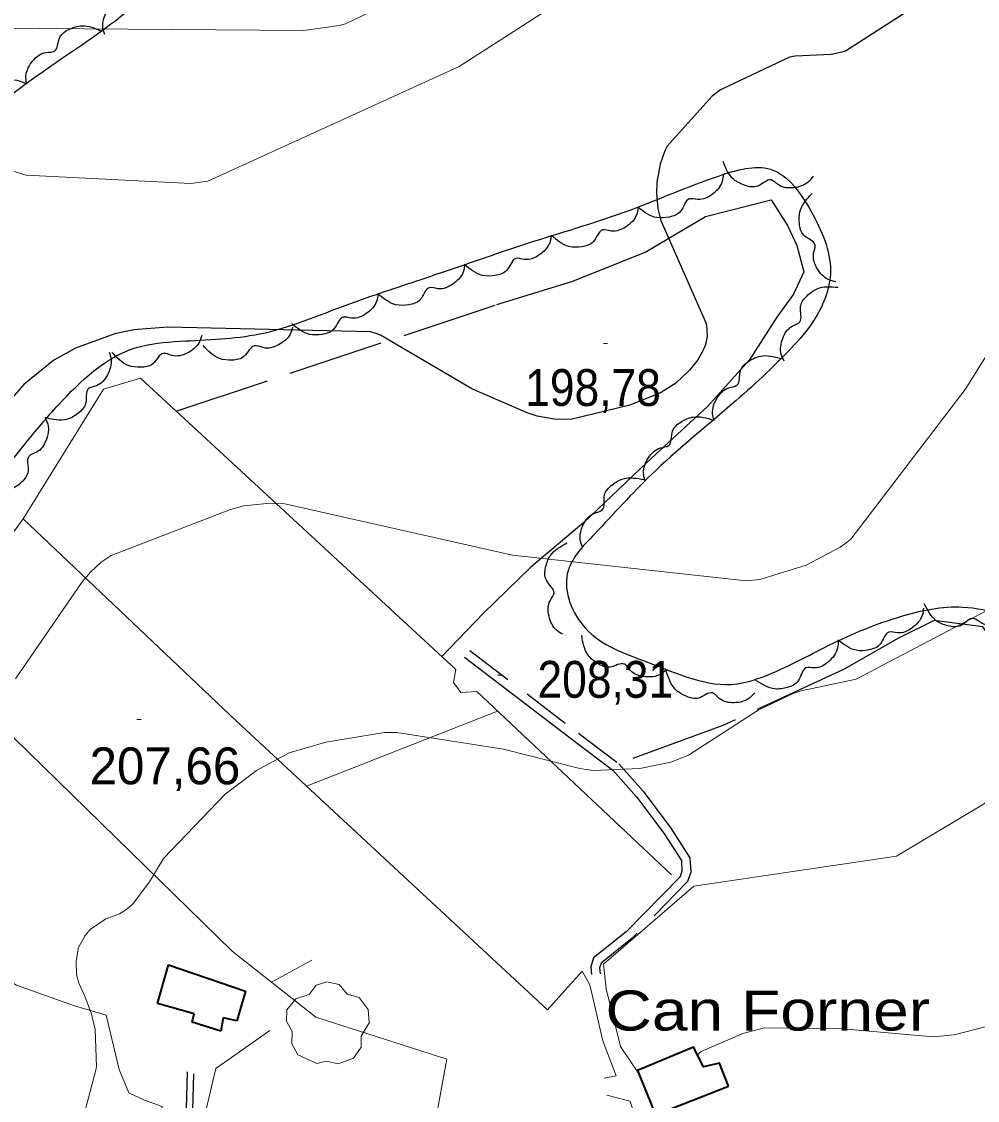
# Model space of a CAD drawing. Extents: x 480269 to 484877, y 4383588 to 4386804.
# Drawn here: x 482297.9 to 482524.9, y 4385133.1 to 4385389.2 of the extents above; entities that cross this region are included whole.
import ezdxf

# ---------------------------------------------------------------- set-up
doc = ezdxf.new("R2010")
doc.units = 0
doc.header["$LTSCALE"] = 3.8
doc.linetypes.add('LONG_DASHED', pattern=[7.5, 6, -1.5])
doc.linetypes.add('MEDIUM_DASHED', pattern=[4.5, 3, -1.5])
for name, color, linetype, lineweight in [('25', 7, 'LONG_DASHED', 25), ('27', 7, 'Continuous', 25), ('29', 7, 'Continuous', 13), ('38', 7, 'Continuous', 25), ('47', 7, 'Continuous', 35), ('49', 7, 'LONG_DASHED', 35), ('51', 7, 'Continuous', 13), ('7', 7, 'Continuous', 13), ('8', 7, 'Continuous', 25), ('9', 7, 'Continuous', 13)]:
    doc.layers.add(name, color=color, linetype=linetype, lineweight=lineweight)
doc.layers.add('5', color=7, linetype='Continuous')

msp = doc.modelspace()

# ---------------------------------------------------------------- linework, layer by layer
at = {"layer": '25'}
for points in [[(482334.67, 4385296.71), (482410.77, 4385322), (482428.81, 4385327.56), (482446.01, 4385334.45), (482460.32, 4385342.91), (482475.93, 4385346.89), (482479.8, 4385340.74), (482482, 4385336.01), (482483.67, 4385329.75), (482481.22, 4385324.46), (482477.28, 4385319.01), (482470.76, 4385308.85), (482460.91, 4385297.89), (482446.35, 4385284.46), (482431.47, 4385270.29), (482418.89, 4385259.64), (482407.54, 4385248.66), (482397.7, 4385238.43)], [(482545.45, 4385218.77), (482535.72, 4385231.68), (482530.93, 4385238.87), (482526.16, 4385245.48), (482514.65, 4385247.03), (482506.2, 4385242.78), (482493.24, 4385235.48), (482464.45, 4385222.09), (482439.95, 4385213.07)]]:
    msp.add_lwpolyline(points, dxfattribs=at)
at = {"layer": '27'}
for points in [[(482134.14, 4385639.56), (482145.42, 4385616.05), (482167.98, 4385611.34), (482199.94, 4385629.21), (482256.34, 4385654.6), (482299.58, 4385676.23), (482309.92, 4385675.29), (482324.96, 4385660.25), (482353.16, 4385626.39), (482366.32, 4385607.58), (482355.04, 4385597.24), (482347.52, 4385585.01), (482347.52, 4385561.5), (482356.92, 4385553.04), (482382.29, 4385553.98), (482400.15, 4385553.98), (482414.25, 4385537.05), (482418.01, 4385522), (482407.67, 4385512.6), (482383.23, 4385513.54), (482370.08, 4385507.9), (482358.8, 4385494.73), (482359.74, 4385477.8), (482342.82, 4385454.29), (482257.28, 4385376.24), (482191.48, 4385317.93), (482156.7, 4385290.66), (482136.02, 4385273.73), (482119.1, 4385272.79), (482113.46, 4385285.02), (482126.62, 4385312.29), (482143.54, 4385346.14), (482160.46, 4385378.12), (482156.7, 4385395.99), (482134.14, 4385407.27), (482113.46, 4385416.68), (482093.72, 4385412.91), (482087.14, 4385401.63), (482072.1, 4385398.81), (482050.48, 4385407.27), (482035.44, 4385408.21), (482021.34, 4385395.05), (482005.36, 4385398.81), (482011, 4385429.84), (482001.6, 4385476.86), (481971.52, 4385519.18), (481936.74, 4385563.38), (481930.16, 4385579.37), (481941.44, 4385597.24), (481940.5, 4385616.99), (481916.06, 4385648.96), (481908.54, 4385674.35), (481928.28, 4385695.98), (481936.74, 4385694.1), (481957.42, 4385664.01), (481967.76, 4385648.02), (481979.04, 4385640.5), (481992.2, 4385648.02), (482008.18, 4385667.77), (482022.28, 4385668.71), (482035.44, 4385653.66), (482062.7, 4385651.78), (482096.54, 4385655.54), (482120.04, 4385653.66), (482134.14, 4385639.56)], [(482987.06, 4385196.22), (482962.01, 4385203.27), (482933.82, 4385208.75), (482918.16, 4385210.32), (482910.33, 4385217.37), (482911.12, 4385227.55), (482911.12, 4385236.17), (482900.16, 4385244), (482857.87, 4385258.89), (482836.73, 4385270.64), (482824.21, 4385265.15), (482832.82, 4385247.14), (482820.29, 4385239.3), (482767.05, 4385239.3), (482715.37, 4385240.87), (482694.23, 4385249.49), (482675.44, 4385265.94), (482679.36, 4385287.09), (482678.57, 4385302.75), (482650.39, 4385311.37), (482636.29, 4385330.17), (482633.95, 4385351.32), (482617.5, 4385368.55), (482588.53, 4385379.52), (482572.87, 4385393.62), (482558.78, 4385411.63), (482539.21, 4385429.65), (482525.9, 4385448.45), (482516.5, 4385468.82), (482492.23, 4385501.72), (482482.83, 4385522.08), (482488.31, 4385537.75), (482533.73, 4385569.87), (482542.34, 4385576.13)], [(482625.51, 4385282.56), (482642.43, 4385259.65), (482650.38, 4385244.64), (482647.78, 4385242.37), (482636.62, 4385237.32), (482619.6, 4385231), (482606.07, 4385227.49), (482592.32, 4385225.27), (482576.02, 4385223.66), (482565.3, 4385225.16), (482544.25, 4385237.98), (482530.74, 4385248.12), (482521.45, 4385250.21), (482506.84, 4385248), (482489.75, 4385241.2), (482474.05, 4385233.67), (482467.83, 4385231.98), (482446.42, 4385237.18), (482431.83, 4385245.15), (482427.52, 4385258.1), (482433.95, 4385267.51), (482447.44, 4385281.6), (482466.7, 4385298.44), (482480.68, 4385311.65), (482486, 4385318.16), (482489.98, 4385329.2), (482485.82, 4385343.36), (482475.74, 4385354.14), (482463.65, 4385352.6), (482442.18, 4385344.35), (482419.61, 4385337.03), (482392.84, 4385327.98), (482375.42, 4385322.04), (482354.47, 4385315.04), (482335.63, 4385313.3), (482324.91, 4385311.71), (482306.75, 4385298.27), (482298.77, 4385288.95), (482284.61, 4385269.24), (482273.64, 4385250.87), (482262.03, 4385234.12), (482247.6, 4385214.12), (482240.37, 4385209.68), (482231.84, 4385210.09), (482210.78, 4385220.1), (482179.62, 4385233.3), (482175.12, 4385239.41), (482174.28, 4385251.32), (482183.7, 4385264.71), (482206.93, 4385288.25), (482225.02, 4385306.72), (482255.15, 4385335.95), (482274.61, 4385354.56), (482305.02, 4385378.68), (482323.6, 4385392.1), (482343.47, 4385412.74), (482356.09, 4385425.44), (482370.63, 4385438.23), (482383.14, 4385448.74), (482409.87, 4385473.1), (482434.85, 4385494.28), (482448.48, 4385499.91), (482458.21, 4385495.14), (482469.07, 4385482.48), (482479.65, 4385471.01), (482489.49, 4385457.47), (482504.85, 4385438.05), (482518.31, 4385421.58), (482537.64, 4385396.47), (482552.32, 4385375.39), (482572.69, 4385353.07), (482605.31, 4385309.46), (482625.51, 4385282.56)], [(482317.71, 4385386.09), (482317.25, 4385387.81), (482318.15, 4385391.49), (482320.81, 4385394.05), (482322.73, 4385394.77), (482323.4, 4385398.26), (482325.26, 4385400.6), (482327.96, 4385401.95), (482332.91, 4385401.59)], [(482299.1, 4385374.63), (482298.98, 4385376.4), (482300.58, 4385379.84), (482303.68, 4385381.84), (482305.71, 4385382.17), (482307.04, 4385385.47), (482309.32, 4385387.39), (482312.24, 4385388.2), (482317.02, 4385386.88)], [(482282.12, 4385361.1), (482281.88, 4385362.86), (482283.26, 4385366.4), (482286.23, 4385368.58), (482288.23, 4385369.04), (482289.35, 4385372.42), (482291.51, 4385374.48), (482294.37, 4385375.47), (482299.22, 4385374.46)], [(482485.92, 4385352.51), (482484.78, 4385351.14), (482481.26, 4385349.74), (482477.63, 4385350.43), (482475.93, 4385351.59), (482472.7, 4385350.11), (482469.72, 4385350.29), (482467.05, 4385351.71), (482464.49, 4385355.96)], [(482464.58, 4385352.97), (482464.3, 4385351.21), (482461.98, 4385348.21), (482458.51, 4385346.96), (482456.46, 4385347.08), (482454.43, 4385344.16), (482451.78, 4385342.79), (482448.76, 4385342.65), (482444.39, 4385345)], [(482491.31, 4385327.43), (482489.59, 4385327.89), (482486.87, 4385330.53), (482486.01, 4385334.12), (482486.36, 4385336.14), (482483.68, 4385338.48), (482482.62, 4385341.27), (482482.81, 4385344.29), (482485.63, 4385348.37)], [(482444.37, 4385345.05), (482443.98, 4385343.32), (482441.47, 4385340.48), (482437.92, 4385339.45), (482435.89, 4385339.71), (482433.67, 4385336.93), (482430.94, 4385335.73), (482427.91, 4385335.79), (482423.71, 4385338.42)], [(482423.71, 4385338.41), (482423.34, 4385336.67), (482420.87, 4385333.79), (482417.34, 4385332.72), (482415.3, 4385332.95), (482413.13, 4385330.14), (482410.41, 4385328.9), (482407.39, 4385328.92), (482403.14, 4385331.48)], [(482403.15, 4385331.47), (482402.79, 4385329.73), (482400.32, 4385326.85), (482396.79, 4385325.77), (482394.75, 4385326), (482392.58, 4385323.18), (482389.86, 4385321.95), (482386.84, 4385321.96), (482382.59, 4385324.52)], [(482479.04, 4385308.59), (482478.33, 4385310.21), (482478.68, 4385313.99), (482480.94, 4385316.91), (482482.73, 4385317.9), (482482.88, 4385321.46), (482484.39, 4385324.03), (482486.86, 4385325.77), (482491.81, 4385326.13)], [(482382.6, 4385324.5), (482382.24, 4385322.76), (482379.79, 4385319.87), (482376.26, 4385318.78), (482374.22, 4385319), (482372.06, 4385316.17), (482369.34, 4385314.93), (482366.32, 4385314.93), (482362.07, 4385317.48)], [(482362.28, 4385316.66), (482361.71, 4385314.98), (482358.91, 4385312.42), (482355.28, 4385311.78), (482353.28, 4385312.25), (482350.78, 4385309.72), (482347.94, 4385308.82), (482344.94, 4385309.2), (482341.03, 4385312.26)], [(482340.72, 4385314.66), (482340.11, 4385312.99), (482337.27, 4385310.48), (482333.62, 4385309.92), (482331.63, 4385310.43), (482329.08, 4385307.95), (482326.22, 4385307.11), (482323.23, 4385307.55), (482319.38, 4385310.69)], [(482318.71, 4385310.73), (482319.19, 4385309.02), (482318.33, 4385305.32), (482315.7, 4385302.74), (482313.78, 4385302), (482313.15, 4385298.5), (482311.31, 4385296.15), (482308.62, 4385294.76), (482303.67, 4385295.08)], [(482462.39, 4385294.44), (482462.01, 4385296.17), (482463.08, 4385299.81), (482465.86, 4385302.24), (482467.81, 4385302.87), (482468.64, 4385306.33), (482470.62, 4385308.57), (482473.38, 4385309.79), (482478.31, 4385309.19)], [(482303.46, 4385295.24), (482304.15, 4385293.6), (482303.75, 4385289.83), (482301.46, 4385286.94), (482299.65, 4385285.96), (482299.46, 4385282.41), (482297.93, 4385279.85), (482295.43, 4385278.15), (482290.48, 4385277.85)], [(482445.94, 4385280.28), (482445.61, 4385282.03), (482446.78, 4385285.64), (482449.63, 4385287.98), (482451.6, 4385288.55), (482452.53, 4385291.98), (482454.57, 4385294.17), (482457.37, 4385295.31), (482462.27, 4385294.57)], [(482431.13, 4385264.41), (482430.61, 4385266.11), (482431.37, 4385269.83), (482433.93, 4385272.48), (482435.83, 4385273.27), (482436.36, 4385276.79), (482438.14, 4385279.19), (482440.79, 4385280.64), (482445.75, 4385280.46)], [(482426.47, 4385243.73), (482424.98, 4385244.69), (482423.18, 4385248.03), (482423.44, 4385251.71), (482424.38, 4385253.53), (482422.54, 4385256.57), (482422.36, 4385259.55), (482423.45, 4385262.37), (482427.37, 4385265.41)], [(482512.1, 4385249.97), (482511.79, 4385248.22), (482509.42, 4385245.26), (482505.92, 4385244.07), (482503.88, 4385244.23), (482501.79, 4385241.35), (482499.12, 4385240.03), (482496.1, 4385239.94), (482491.77, 4385242.37)], [(482533.9, 4385249.17), (482532.87, 4385247.72), (482529.46, 4385246.06), (482525.79, 4385246.47), (482524.01, 4385247.5), (482520.9, 4385245.78), (482517.91, 4385245.73), (482515.14, 4385246.95), (482512.27, 4385250.99)], [(482451.03, 4385235.31), (482449.62, 4385234.23), (482445.87, 4385233.66), (482442.49, 4385235.15), (482441.09, 4385236.66), (482437.61, 4385235.95), (482434.75, 4385236.79), (482432.47, 4385238.78), (482430.93, 4385243.49)], [(482491.83, 4385242.2), (482491.68, 4385240.43), (482489.59, 4385237.27), (482486.22, 4385235.77), (482484.17, 4385235.74), (482482.36, 4385232.68), (482479.81, 4385231.12), (482476.81, 4385230.76), (482472.28, 4385232.79)], [(482472.03, 4385229.85), (482470.79, 4385228.58), (482467.15, 4385227.49), (482463.6, 4385228.5), (482462.01, 4385229.8), (482458.66, 4385228.6), (482455.71, 4385229.04), (482453.17, 4385230.68), (482450.99, 4385235.14)]]:
    msp.add_spline(points, degree=3, dxfattribs=at)
at = {"layer": '29'}
msp.add_lwpolyline([(482368.06, 4385141.82), (482363.52, 4385143.94), (482362.11, 4385146.48), (482362.21, 4385149.46), (482360.84, 4385151.87), (482360.88, 4385154.62), (482363.04, 4385157.22), (482366.23, 4385158.22), (482367.88, 4385160.41), (482370.45, 4385161.24), (482373.31, 4385160.59), (482375.26, 4385158.32), (482378.07, 4385157.5), (482380.2, 4385154.65), (482380.44, 4385151.52), (482378.56, 4385148.37), (482378.56, 4385145.69), (482376.74, 4385143.08), (482373.12, 4385141.74), (482370.35, 4385142.37)], close=True, dxfattribs=at)
at = {"layer": '38', "linetype": 'MEDIUM_DASHED'}
for points in [[(482404.34, 4385239.92), (482430.2, 4385220.26), (482439.75, 4385212.98), (482445.55, 4385206.47), (482452.14, 4385197.67), (482456.63, 4385190.68), (482456.83, 4385187.26), (482456.09, 4385185.03), (482442.9, 4385171.58), (482435.52, 4385165.69), (482435.18, 4385164.55), (482435.3, 4385163.12)], [(482317.35, 4385046.44), (482318.97, 4385057.26), (482319.53, 4385063.31), (482319.85, 4385068.28), (482320.92, 4385073.7), (482324.75, 4385084.18), (482330.04, 4385093.91), (482333.15, 4385101.98), (482335.63, 4385111.41), (482337.75, 4385120.36), (482338.55, 4385128.02), (482338.87, 4385139.83)]]:
    msp.add_lwpolyline(points, dxfattribs=at)
at = {"layer": '38'}
for points in [[(482403.08, 4385238.28), (482428.94, 4385218.62), (482438.34, 4385211.45), (482443.95, 4385205.16), (482450.44, 4385196.49), (482454.6, 4385190.02), (482454.74, 4385187.53), (482454.28, 4385186.14), (482441.51, 4385173.11), (482433.72, 4385166.9), (482433.09, 4385164.76), (482433.24, 4385162.94)], [(482315.74, 4385046.34), (482317.4, 4385057.45), (482317.96, 4385063.43), (482318.28, 4385068.48), (482319.4, 4385074.12), (482323.31, 4385084.84), (482328.6, 4385094.57), (482331.65, 4385102.47), (482334.09, 4385111.8), (482336.19, 4385120.63), (482336.98, 4385128.12), (482337.3, 4385139.88)]]:
    msp.add_lwpolyline(points, dxfattribs=at)
at = {"layer": '47'}
msp.add_lwpolyline([(482465.78, 4385136.44), (482463.63, 4385141.91), (482459.83, 4385141.06), (482457.52, 4385145.69), (482444.17, 4385140.18), (482448.43, 4385129.63)], close=True, dxfattribs=at)
at = {"layer": '49'}
msp.add_lwpolyline([(482351.09, 4385159.05), (482349.07, 4385151.96), (482345.8, 4385152.65), (482345.22, 4385149.48), (482338.43, 4385151.68), (482338.93, 4385153.66), (482330.2, 4385156.07), (482332.82, 4385165.24)], close=True, dxfattribs=at)
at = {"layer": '51'}
for p, q in [((482410.95, 4385225.51), (482365.59, 4385207.7)), ((482366.88, 4385166.41), (482357.27, 4385161.17))]:
    msp.add_line(p, q, dxfattribs=at)
for points in [[(482436.25, 4385138.38), (482439.12, 4385138.91), (482435.94, 4385147.21), (482432.87, 4385160.5), (482431.01, 4385163.75), (482422.78, 4385154.58), (482348.88, 4385223.2), (482298.28, 4385271.12), (482317.35, 4385301.92), (482326.21, 4385304.52), (482401.04, 4385235.34), (482400.5, 4385232.31), (482402.26, 4385229.89), (482406, 4385230.15), (482452.27, 4385186.64)], [(482298.28, 4385271.12), (482241.52, 4385192.94), (482296.71, 4385160.42), (482310.52, 4385155.57), (482317.98, 4385153.32), (482321.07, 4385140.39), (482323.42, 4385134.86), (482327.12, 4385133.12), (482331.3, 4385131.64), (482330.14, 4385114.89), (482328.6, 4385105), (482325.35, 4385097.1), (482319.56, 4385089.16), (482309.96, 4385080.87), (482308.11, 4385080.78), (482309.28, 4385094.15)], [(482398.88, 4385142.89), (482367.84, 4385152.87), (482347.9, 4385168.5), (482275.24, 4385239.38)], [(482526.74, 4385203.65), (482505.68, 4385191.08), (482457.54, 4385183.92), (482436.12, 4385165.4), (482436.77, 4385159.55), (482440.12, 4385145.86), (482444.42, 4385139.56)], [(482356.88, 4385149.69), (482344.03, 4385140.66), (482341.68, 4385130.61), (482337.92, 4385114.87), (482332.34, 4385098.69), (482326.96, 4385085.88), (482324.21, 4385078.51)], [(482396.69, 4385112.77), (482395.36, 4385123.45), (482398.88, 4385142.89)], [(482436.91, 4385134.3), (482442.42, 4385132.92), (482445.18, 4385123.98), (482434.19, 4385116.07)]]:
    msp.add_lwpolyline(points, dxfattribs=at)
at = {"layer": '7'}
for p, q in [((482436.1, 4385312.78), (482437.1, 4385312.78)), ((482410.94, 4385234.02), (482411.94, 4385234.02)), ((482325.33, 4385223.47), (482326.33, 4385223.47))]:
    msp.add_line(p, q, dxfattribs=at)
at = {"layer": '8'}
msp.add_lwpolyline([(482523.69, 4385401.52), (482493.55, 4385382.17), (482492.39, 4385381.81), (482490.16, 4385381.38), (482481.61, 4385380.96), (482480.25, 4385380.7), (482463.93, 4385372.99), (482461.95, 4385371.51), (482451.22, 4385359.58), (482450.67, 4385358.48), (482449.54, 4385355.37), (482448.79, 4385351.1), (482448.7, 4385348.4), (482449.02, 4385344.78), (482449.74, 4385341.93), (482460.49, 4385317.49), (482460.69, 4385316.17), (482460.7, 4385314.46), (482460.49, 4385313.14), (482460.24, 4385312.29), (482459.72, 4385311), (482458.54, 4385308.91), (482456.56, 4385306.43), (482453.28, 4385303.33), (482449.64, 4385301.05), (482442.4, 4385298.09), (482428.37, 4385294.75), (482424.37, 4385294.81), (482420.37, 4385295.49), (482417.97, 4385296.28), (482404.87, 4385301.98), (482383.18, 4385314.76), (482382.11, 4385315.15), (482380.76, 4385315.5), (482332.65, 4385316.62), (482324.59, 4385316.04), (482320.04, 4385315.06), (482310.72, 4385311.62), (482305.58, 4385308.78), (482298.43, 4385303.01), (482292.9, 4385296.67)], dxfattribs=at)
at = {"layer": '9'}
for points in [[(482428.86, 4385395.96), (482401.85, 4385378.5), (482342.17, 4385351.28), (482338.12, 4385350.75), (482299.06, 4385352.7), (482271.73, 4385360.95), (482258.34, 4385363.07), (482251.06, 4385363.15), (482248, 4385362.68)], [(482381.13, 4385391.67), (482374.87, 4385388.64), (482373.35, 4385388.24), (482364.95, 4385387.08), (482249.91, 4385387.92), (482244.13, 4385389.71)], [(482529.46, 4385313.75), (482522.03, 4385301.87), (482494.87, 4385266.35), (482493.66, 4385265.34), (482492.28, 4385264.38), (482484.26, 4385260.11), (482473.24, 4385256.75), (482469.98, 4385256.46), (482414.54, 4385262.54), (482360.48, 4385274.73), (482356.13, 4385274.79), (482350.73, 4385274.2), (482347.57, 4385273.39), (482319.18, 4385262.47), (482316.86, 4385260.84), (482314.29, 4385258.46), (482312.34, 4385256.17), (482296.48, 4385233.14)], [(482458.41, 4385143.92), (482458.85, 4385144.33), (482459.31, 4385144.69), (482469.21, 4385148.98), (482474.32, 4385150.31), (482492.92, 4385150.1), (482514.44, 4385148.2), (482519.37, 4385148.64), (482527.09, 4385150.59), (482529.52, 4385151.66), (482558.41, 4385174.54), (482606.68, 4385208.97), (482633.44, 4385223.54), (482636.21, 4385225.64), (482647.54, 4385237.72), (482663.35, 4385248.31), (482697.04, 4385270.64)], [(482543.13, 4385257.8), (482496.08, 4385233.07), (482483.04, 4385230.29), (482481.17, 4385229.67), (482472.82, 4385225.73), (482456.31, 4385215.06), (482452.07, 4385213.35), (482444.77, 4385211.87), (482433.66, 4385211.42), (482430.46, 4385211.89), (482412.37, 4385216.44), (482387.02, 4385220.45), (482384.14, 4385220.43), (482370.17, 4385218.14), (482361.51, 4385215.57), (482353.7, 4385211.36), (482346.3, 4385205.79), (482331.63, 4385190.53)], [(482331.63, 4385190.53), (482328.27, 4385185), (482324.45, 4385179.82), (482323.78, 4385179.18), (482322.48, 4385178.17), (482321.18, 4385177.41), (482318.04, 4385176.2), (482317.95, 4385176.18), (482314.19, 4385173.68), (482313.05, 4385172.2), (482311.48, 4385169.36), (482310.92, 4385166.14), (482311, 4385162.96), (482311.49, 4385160.94), (482312.98, 4385157.8), (482314.56, 4385153.59), (482315.4, 4385149.88), (482315.71, 4385141.15), (482315.52, 4385139.95), (482306.04, 4385104.55)]]:
    msp.add_lwpolyline(points, dxfattribs=at)

# ---------------------------------------------------------------- texts
at = {"layer": '5', "width": 1.2}
msp.add_text('Can Forner', height=9.5, dxfattribs=at).set_placement((482436.58, 4385149.67))
at = {"layer": '7', "width": 0.9}
for s, p in [('198,78', (482417.52, 4385297.93)), ('208,31', (482420.44, 4385228.66))]:
    msp.add_text(s, height=8.75, dxfattribs=at).set_placement(p)
at = {"layer": '7'}
msp.add_text('207,66', height=8.75, dxfattribs=at).set_placement((482314.08, 4385208.12))

doc.saveas('drawing.dxf')
